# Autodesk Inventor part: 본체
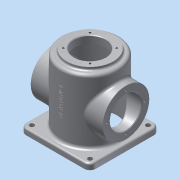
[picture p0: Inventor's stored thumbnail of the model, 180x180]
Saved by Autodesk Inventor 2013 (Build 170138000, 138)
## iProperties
Created: 2015-10
Part Number: 본체
Material: 알루미늄 6061
Document SubType Name: Modeling
Designer: dgall
Density: 2.71 g/cm^3
Mass: 985.997 g
Surface Area: 1037.35 cm^2
Volume: 363.836 cm^3
Author: dgall
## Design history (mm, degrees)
sketch "스케치1"
  geometry: L1 (-60, 60)-(60, 60); L2 (60, 60)-(60, -60); L3 (60, -60)-(-60, -60); L4 (-60, -60)-(-60, 60); L5 (-60, 60)-(60, -60); L6 (60, 60)-(-60, -60); C1 r 50 at (0, 0); C2 r 40 at (0, 0); C3 r 27 at (0, 0); 1 further point
  constraints: 12 end point, 3 centre point, 3 coincident, 2 midpoint, 2 parallel, 2 perpendicular, 1 horizontal
  dimensions: "d0" = 120 distance of L1.start L1.end; "d2" = 100 diameter of C1; "d3" = 40 radius of C2; "d4" = 27 radius of C3
extrude "돌출1" new body sketch "스케치1" distance "d5" = 10; taper "d6" = 0 deg
extrude "돌출2" join sketch "스케치1" distance "d7" = 110; taper "d8" = 0 deg
extrude "돌출3" join sketch "스케치1" distance "d9" = 115; taper "d10" = 0 deg
extrude "돌출5" cut sketch "스케치1" stored distance "d15" = 112; taper "d16" = 0 deg
sketch "스케치4"
  geometry: L1 (-60, -10)-(60, -10) reference; C1 r 40 at (0, 50); 1 further point
  constraints: 1 centre point, 1 vertical alignment
  dimensions: "d21" = 40 radius of C1; "d22" = 60 distance from line of L1 C1.centre
extrude "돌출7" join sketch "스케치4" stored distance "d23" = 124; taper "d24" = 0 deg
sketch "스케치5"
  geometry: C1 r 45 at (0, 0); 1 further point
  constraints: 1 centre point, 1 coincident
  dimensions: "d25" = 45 radius of C1
extrude "돌출8" cut sketch "스케치5" distance "d26" = 112; taper "d27" = 0 deg
hole "구멍1" diameter "d30" = 54; stored, may be unused: countersink angle "d34" = 90 deg, drill point angle "d36" = 118 deg; dims "d28" = 10, "d29" = 10, "d31" = 6, "d32" = 4, "d33" = 2, "d35" = 8
sketch "스케치6"
  geometry: C1 r 27 at (0, 0) reference; 2 further points
  constraints: 1 horizontal alignment
  dimensions: "d37" = 32.5 distance of point (32.5, 0) C1.centre
hole "구멍2" sketch "스케치6" at (32.5, 0) diameter "d38" = 3.242; stored, may be unused: countersink angle "d42" = 90 deg, drill point angle "d44" = 118 deg; dims "d39" = 8, "d40" = 4, "d41" = 2, "d43" = 10
chamfer "모따기1" distance "d48" = 3; stored, may be unused: second distance "d49" = 2, angle "d50" = 45 deg
chamfer "모따기2" distance "d51" = 1; stored, may be unused: second distance "d52" = 2, angle "d53" = 45 deg
fillet "모깎기1" dims "d54" = 10
fillet "모깎기2" dims "d55" = 5, "d56" = 3
sketch "스케치7"
  geometry: A1 r 7 centre (-50, -50) between (-57, -50) and (-50, -57) reference; A2 r 7 centre (50, -50) between (50, -57) and (57, -50) reference; A3 r 7 centre (50, 50) between (57, 50) and (50, 57) reference; A4 r 7 centre (-50, 50) between (-50, 57) and (-57, 50) reference
hole "구멍3" sketch "스케치7" at (-50, -50), (50, -50), (50, 50), (-50, 50) diameter "d57" = 8; stored, may be unused: countersink angle "d61" = 90 deg, drill point angle "d63" = 118 deg; dims "d58" = 8, "d59" = 4, "d60" = 2, "d62" = 10
node "작업 평면1"
sketch "스케치8"
  geometry: L1 (50, -10)-(-50, -10) reference; 2 further points
  constraints: 1 vertical alignment, 1 other
  dimensions: "d64" = 70 distance from line of L1 point (0, 60)
feature "엠보싱1" sketch "스케치8" dims "d0" = 120, "d65" = 0.5, "d66" = 0
sketch "스케치10"
  geometry: L1 (-75.861, 0)-(0, 0); L2 (0, 0)-(-63.373, 63.373); C1 r 40 at (0, 0) reference; C2 r 28 at (0, 0) reference; 1 further point
  constraints: 4 end point, 1 horizontal, 1 point on line
  dimensions: "d80" = 45 deg angle of L1 L2; "d81" = 32.5 distance of C1.centre point (-22.981, 22.981)
hole "구멍5" sketch "스케치10" at (-22.981, 22.981) diameter "d82" = 3.242; stored, may be unused: countersink angle "d86" = 90 deg, drill point angle "d88" = 118 deg; dims "d83" = 8, "d84" = 4, "d85" = 2, "d87" = 10
node "솔리드1"
pattern_circular "원형 패턴1" dims angle "d46" = 360 deg
mirror "대칭1"
pattern_circular "원형 패턴3" dims angle "d90" = 360 deg
